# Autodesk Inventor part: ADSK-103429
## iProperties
Shininess: 0.0
Created: 2000-09
Part Number: ADSK-103429
Document SubType Name: Modeling
Stock Number: ADSK-103429
Density: 1 g/cm^3
Density: 0.0
Volumn: 0.0
Area: 0.0
PropertySet Name: Model Information
Control State: 0
Master: False
Checked Out: False
Author: gao
